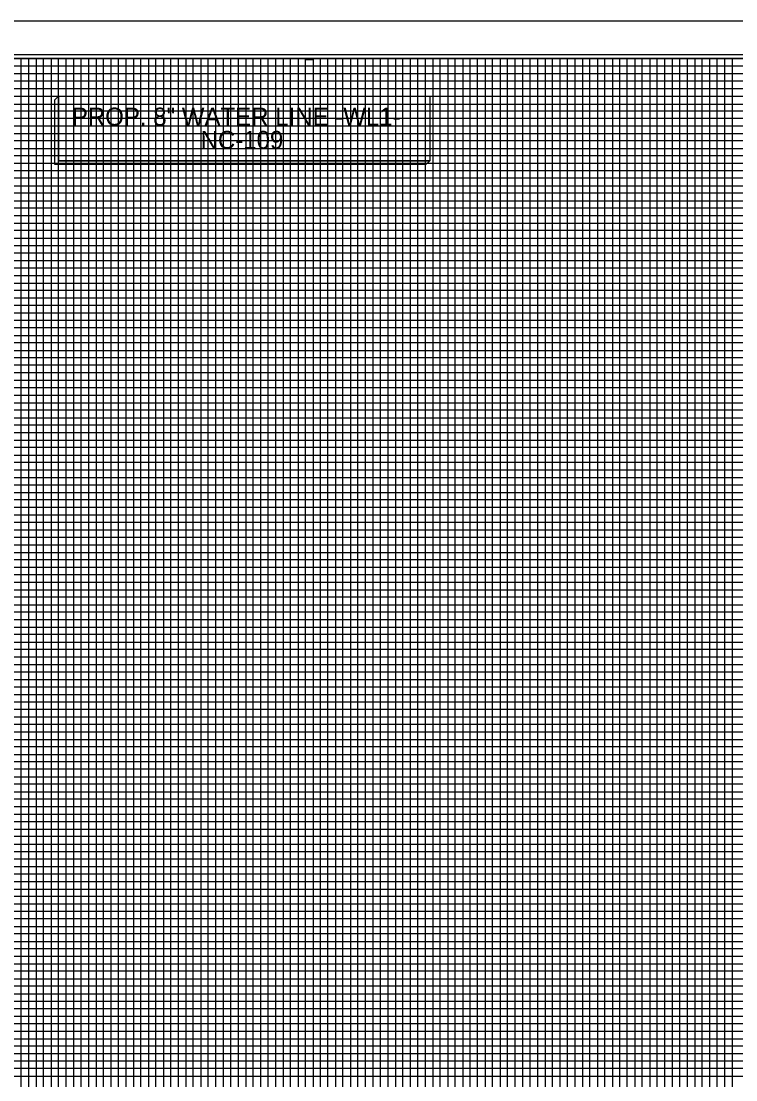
# Model space of a CAD drawing. Extents: x 3814791 to 3815465, y 1224203 to 1224643.
# Drawn here: x 3815088.1 to 3815279.1, y 1224360.2 to 1224643.2 of the extents above; entities that cross this region are included whole.
import ezdxf

# ---------------------------------------------------------------- set-up
doc = ezdxf.new("R2010")
doc.units = 0
for name, color, linetype in [('COGO Default Chain', 7, 'Continuous'), ('Exist Roads EOP', 7, 'Continuous'), ('Pattern 49', 7, 'Continuous'), ('Scratch_Level_1', 7, 'Continuous')]:
    doc.layers.add(name, color=color, linetype=linetype)

msp = doc.modelspace()

# ---------------------------------------------------------------- linework, layer by layer
at = {"layer": 'COGO Default Chain'}
for p, q in [((3815097.11, 1224622.19), (3815098.11, 1224623.19)), ((3815197.29, 1224605.91), (3815196.29, 1224604.91)), ((3815197.29, 1224605.91), (3815196.29, 1224604.91))]:
    msp.add_line(p, q, dxfattribs=at)
msp.add_lwpolyline([(3815098.11, 1224623.19), (3815197.29, 1224623.19), (3815197.29, 1224605.91), (3815098.11, 1224605.91)], close=True, dxfattribs=at)
for points in [[(3815098.11, 1224623.19), (3815098.11, 1224605.91), (3815197.29, 1224605.91)], [(3815196.29, 1224604.91), (3815097.11, 1224604.91), (3815097.11, 1224622.19)]]:
    msp.add_lwpolyline(points, dxfattribs=at)
at = {"layer": 'Exist Roads EOP'}
for p, q in [((3814878.11, 1224633.21), (3815378.11, 1224633.21)), ((3815438.11, 1224561.21), (3814878.11, 1224561.21)), ((3814878.11, 1224559.21), (3815438.11, 1224559.21)), ((3815438.11, 1224551.21), (3814878.11, 1224551.21))]:
    msp.add_line(p, q, dxfattribs=at)
for points in [[(3815458.11, 1224633.21), (3814858.11, 1224633.21), (3814858.11, 1224213.21), (3815458.11, 1224213.21)], [(3814878.11, 1224633.21), (3814878.11, 1224223.21), (3815438.11, 1224223.21), (3815438.11, 1224578.19), (3815378.11, 1224578.19), (3815378.11, 1224633.21)]]:
    msp.add_lwpolyline(points, close=True, dxfattribs=at)
for points in [[(3815088.11, 1224223.21), (3815088.11, 1224633.21), (3815108.11, 1224633.21), (3815108.11, 1224223.21)], [(3815090.11, 1224223.21), (3815090.11, 1224633.21), (3815092.11, 1224633.21), (3815092.11, 1224223.21)], [(3815094.11, 1224223.21), (3815094.11, 1224633.21), (3815096.11, 1224633.21), (3815096.11, 1224223.21)], [(3815098.11, 1224223.21), (3815098.11, 1224633.21), (3815118.11, 1224633.21), (3815118.11, 1224223.21)], [(3815100.11, 1224223.21), (3815100.11, 1224633.21), (3815102.11, 1224633.21), (3815102.11, 1224223.21)], [(3815104.11, 1224223.21), (3815104.11, 1224633.21), (3815106.11, 1224633.21), (3815106.11, 1224223.21)], [(3815110.11, 1224223.21), (3815110.11, 1224633.21), (3815112.11, 1224633.21), (3815112.11, 1224223.21)], [(3815114.11, 1224223.21), (3815114.11, 1224633.21), (3815116.11, 1224633.21), (3815116.11, 1224223.21)], [(3815120.11, 1224223.21), (3815120.11, 1224633.21), (3815122.11, 1224633.21), (3815122.11, 1224223.21)], [(3815124.11, 1224223.21), (3815124.11, 1224633.21), (3815126.11, 1224633.21), (3815126.11, 1224223.21)], [(3815128.11, 1224223.21), (3815128.11, 1224633.21), (3815148.11, 1224633.21), (3815148.11, 1224223.21)], [(3815130.11, 1224223.21), (3815130.11, 1224633.21), (3815132.11, 1224633.21), (3815132.11, 1224223.21)], [(3815134.11, 1224223.21), (3815134.11, 1224633.21), (3815136.11, 1224633.21), (3815136.11, 1224223.21)], [(3815138.11, 1224223.21), (3815138.11, 1224633.21), (3815158.11, 1224633.21), (3815158.11, 1224223.21)], [(3815140.11, 1224223.21), (3815140.11, 1224633.21), (3815142.11, 1224633.21), (3815142.11, 1224223.21)], [(3815144.11, 1224223.21), (3815144.11, 1224633.21), (3815146.11, 1224633.21), (3815146.11, 1224223.21)], [(3815150.11, 1224223.21), (3815150.11, 1224633.21), (3815152.11, 1224633.21), (3815152.11, 1224223.21)], [(3815154.11, 1224223.21), (3815154.11, 1224633.21), (3815156.11, 1224633.21), (3815156.11, 1224223.21)], [(3815160.11, 1224223.21), (3815160.11, 1224633.21), (3815162.11, 1224633.21), (3815162.11, 1224223.21)], [(3815164.11, 1224223.21), (3815164.11, 1224632.97), (3815166.11, 1224632.97), (3815166.11, 1224223.21)], [(3815168.11, 1224223.21), (3815168.11, 1224633.21), (3815188.11, 1224633.21), (3815188.11, 1224223.21)], [(3815170.11, 1224223.21), (3815170.11, 1224633.21), (3815172.11, 1224633.21), (3815172.11, 1224223.21)], [(3815174.11, 1224223.21), (3815174.11, 1224633.21), (3815176.11, 1224633.21), (3815176.11, 1224223.21)], [(3815178.11, 1224223.21), (3815178.11, 1224633.21), (3815198.11, 1224633.21), (3815198.11, 1224223.21)], [(3815180.11, 1224223.21), (3815180.11, 1224633.21), (3815182.11, 1224633.21), (3815182.11, 1224223.21)], [(3815184.11, 1224223.21), (3815184.11, 1224633.21), (3815186.11, 1224633.21), (3815186.11, 1224223.21)], [(3815190.11, 1224223.21), (3815190.11, 1224633.21), (3815192.11, 1224633.21), (3815192.11, 1224223.21)], [(3815194.11, 1224223.21), (3815194.11, 1224633.21), (3815196.11, 1224633.21), (3815196.11, 1224223.21)], [(3815200.11, 1224223.21), (3815200.11, 1224633.21), (3815202.11, 1224633.21), (3815202.11, 1224223.21)], [(3815204.11, 1224223.21), (3815204.11, 1224633.21), (3815206.11, 1224633.21), (3815206.11, 1224223.21)], [(3815208.11, 1224223.21), (3815208.11, 1224633.21), (3815228.11, 1224633.21), (3815228.11, 1224223.21)], [(3815210.11, 1224223.21), (3815210.11, 1224633.21), (3815212.11, 1224633.21), (3815212.11, 1224223.21)], [(3815214.11, 1224223.21), (3815214.11, 1224633.21), (3815216.11, 1224633.21), (3815216.11, 1224223.21)], [(3815218.11, 1224223.21), (3815218.11, 1224633.21), (3815238.11, 1224633.21), (3815238.11, 1224223.21)], [(3815220.11, 1224223.21), (3815220.11, 1224633.21), (3815222.11, 1224633.21), (3815222.11, 1224223.21)], [(3815224.11, 1224223.21), (3815224.11, 1224633.21), (3815226.11, 1224633.21), (3815226.11, 1224223.21)], [(3815230.11, 1224223.21), (3815230.11, 1224633.21), (3815232.11, 1224633.21), (3815232.11, 1224223.21)], [(3815234.11, 1224223.21), (3815234.11, 1224633.21), (3815236.11, 1224633.21), (3815236.11, 1224223.21)], [(3815240.11, 1224223.21), (3815240.11, 1224633.21), (3815242.11, 1224633.21), (3815242.11, 1224223.21)], [(3815244.11, 1224223.21), (3815244.11, 1224633.21), (3815246.11, 1224633.21), (3815246.11, 1224223.21)], [(3815248.11, 1224223.21), (3815248.11, 1224633.21), (3815268.11, 1224633.21), (3815268.11, 1224223.21)], [(3815250.11, 1224223.21), (3815250.11, 1224633.21), (3815252.11, 1224633.21), (3815252.11, 1224223.21)], [(3815254.11, 1224223.21), (3815254.11, 1224633.21), (3815256.11, 1224633.21), (3815256.11, 1224223.21)], [(3815258.11, 1224223.21), (3815258.11, 1224633.21), (3815278.11, 1224633.21), (3815278.11, 1224223.21)], [(3815260.11, 1224223.21), (3815260.11, 1224633.21), (3815262.11, 1224633.21), (3815262.11, 1224223.21)], [(3815264.11, 1224223.21), (3815264.11, 1224633.21), (3815266.11, 1224633.21), (3815266.11, 1224223.21)], [(3815270.11, 1224223.21), (3815270.11, 1224633.21), (3815272.11, 1224633.21), (3815272.11, 1224223.21)], [(3815274.11, 1224223.21), (3815274.11, 1224633.21), (3815276.11, 1224633.21), (3815276.11, 1224223.21)], [(3815378.09, 1224631.21), (3814878.11, 1224631.21), (3814878.11, 1224629.21), (3815378.09, 1224629.21)], [(3815378.09, 1224627.21), (3814878.11, 1224627.21), (3814878.11, 1224625.21), (3815378.09, 1224625.21)], [(3815378.09, 1224603.21), (3814858.15, 1224603.21), (3814858.15, 1224623.19), (3815378.09, 1224623.19)], [(3815378.09, 1224620.91), (3814878.11, 1224620.91), (3814878.11, 1224619.21), (3815378.09, 1224619.21)], [(3815378.09, 1224617.21), (3814878.11, 1224617.21), (3814878.11, 1224615.21), (3815378.09, 1224615.21)], [(3814858.11, 1224613.21), (3815378.09, 1224613.21)], [(3815378.09, 1224611.21), (3814878.11, 1224611.21), (3814878.11, 1224609.21), (3815378.09, 1224609.21)], [(3815378.11, 1224607.21), (3814878.11, 1224607.21), (3814878.11, 1224605.21), (3815378.09, 1224605.21)], [(3815378.09, 1224601.21), (3814878.11, 1224601.21), (3814878.11, 1224599.21), (3815378.09, 1224599.21)], [(3815378.09, 1224597.21), (3814878.11, 1224597.21), (3814878.11, 1224595.21), (3815378.09, 1224595.21)], [(3815378.09, 1224593.21), (3814858.11, 1224593.21), (3814858.11, 1224573.19), (3815458.11, 1224573.19)], [(3815378.09, 1224591.21), (3814878.11, 1224591.21), (3814878.11, 1224589.21), (3815378.09, 1224589.21)], [(3815378.09, 1224587.21), (3814878.11, 1224587.21), (3814878.11, 1224585.21), (3815378.09, 1224585.21)], [(3815458.11, 1224563.21), (3814858.11, 1224563.21), (3814858.11, 1224583.21), (3815378.09, 1224583.21)], [(3815378.09, 1224581.21), (3814878.11, 1224581.21), (3814878.11, 1224579.21), (3815378.09, 1224579.21)], [(3815438.11, 1224577.21), (3814878.11, 1224577.21), (3814878.11, 1224577.21), (3814878.11, 1224569.21), (3815438.11, 1224569.21)], [(3815438.11, 1224577.21), (3814878.11, 1224577.21), (3814878.11, 1224577.21), (3814878.11, 1224569.21), (3815458.11, 1224569.21)], [(3814878.11, 1224575.21), (3815438.11, 1224575.21)], [(3815438.11, 1224571.21), (3814878.11, 1224571.21)], [(3815438.11, 1224567.21), (3814878.11, 1224567.21), (3814878.11, 1224565.21), (3815438.11, 1224565.21)], [(3815438.11, 1224557.21), (3814878.11, 1224557.21), (3814878.11, 1224555.21), (3815438.11, 1224555.21)], [(3815458.11, 1224553.21), (3814858.11, 1224553.21), (3814858.11, 1224533.21), (3815458.11, 1224533.21)], [(3815438.11, 1224549.21), (3814878.11, 1224549.21), (3814878.11, 1224547.21), (3815438.11, 1224547.21)], [(3815438.11, 1224545.21), (3814878.11, 1224545.21)], [(3815458.11, 1224523.21), (3814858.11, 1224523.21), (3814858.11, 1224543.21), (3815458.11, 1224543.21)], [(3814878.11, 1224541.21), (3815438.11, 1224541.21)], [(3815438.11, 1224539.21), (3814878.11, 1224539.21), (3814878.11, 1224537.21), (3815438.11, 1224537.21)], [(3815438.11, 1224535.21), (3814878.11, 1224535.21), (3814878.11, 1224531.21), (3815438.11, 1224531.21)], [(3815438.11, 1224529.21), (3814878.11, 1224529.21), (3814878.11, 1224527.21), (3815438.11, 1224527.21)], [(3815438.11, 1224525.21), (3814878.11, 1224525.21), (3814878.11, 1224521.21), (3815438.11, 1224521.21)], [(3815438.11, 1224519.21), (3814878.11, 1224519.21), (3814878.11, 1224517.21), (3815438.11, 1224517.21)], [(3815458.11, 1224513.21), (3814858.11, 1224513.21), (3814858.11, 1224493.21), (3815458.11, 1224493.21)], [(3815438.11, 1224515.21), (3814878.11, 1224515.21), (3814878.11, 1224511.21), (3815438.11, 1224511.21)], [(3815438.11, 1224509.21), (3814878.11, 1224509.21), (3814878.11, 1224507.21), (3815438.11, 1224507.21)], [(3815438.11, 1224505.21), (3814878.11, 1224505.21), (3814878.11, 1224501.21), (3815438.11, 1224501.21)], [(3815458.11, 1224483.21), (3814858.11, 1224483.21), (3814858.11, 1224503.21), (3815458.11, 1224503.21)], [(3815438.11, 1224499.21), (3814878.11, 1224499.21), (3814878.11, 1224497.21), (3815438.11, 1224497.21)], [(3815438.11, 1224495.21), (3814878.11, 1224495.21), (3814878.11, 1224491.21), (3815438.11, 1224491.21)], [(3815438.11, 1224489.21), (3814878.11, 1224489.21), (3814878.11, 1224487.21), (3815438.11, 1224487.21)], [(3815438.11, 1224485.21), (3814878.11, 1224485.21), (3814878.11, 1224481.21), (3815438.11, 1224481.21)], [(3815438.11, 1224479.21), (3814878.11, 1224479.21), (3814878.11, 1224477.21), (3815438.11, 1224477.21)], [(3815458.11, 1224473.21), (3814858.11, 1224473.21), (3814858.11, 1224453.21), (3815458.11, 1224453.21)], [(3815438.11, 1224475.21), (3814878.11, 1224475.21), (3814878.11, 1224471.21), (3815438.11, 1224471.21)], [(3815438.11, 1224469.21), (3814878.11, 1224469.21), (3814878.11, 1224467.21), (3815438.11, 1224467.21)], [(3815438.11, 1224465.21), (3814878.11, 1224465.21), (3814878.11, 1224461.21), (3815438.11, 1224461.21)], [(3815458.11, 1224443.21), (3814858.11, 1224443.21), (3814858.11, 1224463.21), (3815458.11, 1224463.21)], [(3815438.11, 1224459.21), (3814878.11, 1224459.21), (3814878.11, 1224457.21), (3815438.11, 1224457.21)], [(3815438.11, 1224455.21), (3814878.11, 1224455.21), (3814878.11, 1224451.21), (3815438.11, 1224451.21)], [(3815438.11, 1224449.21), (3814878.11, 1224449.21), (3814878.11, 1224447.21), (3815438.11, 1224447.21)], [(3815438.11, 1224445.21), (3814878.11, 1224445.21), (3814878.11, 1224441.21), (3815438.11, 1224441.21)], [(3815438.11, 1224439.21), (3814878.11, 1224439.21), (3814878.11, 1224437.21), (3815438.11, 1224437.21)], [(3815438.11, 1224435.21), (3814878.11, 1224435.21), (3814878.11, 1224431.21), (3815438.11, 1224431.21)], [(3815458.11, 1224433.21), (3814858.11, 1224433.21), (3814858.11, 1224413.21), (3815458.11, 1224413.21)], [(3815438.11, 1224429.21), (3814878.11, 1224429.21), (3814878.11, 1224427.21), (3815438.11, 1224427.21)], [(3815438.11, 1224425.21), (3814878.11, 1224425.21)], [(3815458.11, 1224403.21), (3814858.11, 1224403.21), (3814858.11, 1224423.21), (3815458.11, 1224423.21)], [(3814878.11, 1224421.21), (3815438.11, 1224421.21)], [(3815438.11, 1224419.21), (3814878.11, 1224419.21), (3814878.11, 1224417.21), (3815438.11, 1224417.21)], [(3815438.11, 1224415.21), (3814878.11, 1224415.21), (3814878.11, 1224411.21), (3815438.11, 1224411.21)], [(3815438.11, 1224409.21), (3814878.11, 1224409.21), (3814878.11, 1224407.21), (3815438.11, 1224407.21)], [(3815438.11, 1224405.21), (3814878.11, 1224405.21), (3814878.11, 1224401.21), (3815438.11, 1224401.21)], [(3815438.11, 1224399.21), (3814878.11, 1224399.21), (3814878.11, 1224397.21), (3815438.11, 1224397.21)], [(3815438.11, 1224395.21), (3814878.11, 1224395.21), (3814878.11, 1224391.21), (3815438.11, 1224391.21)], [(3815458.11, 1224393.21), (3814858.11, 1224393.21), (3814858.11, 1224373.21), (3815458.11, 1224373.21)], [(3815438.11, 1224389.21), (3814878.11, 1224389.21), (3814878.11, 1224387.21), (3815438.11, 1224387.21)], [(3815458.11, 1224363.21), (3814858.11, 1224363.21), (3814858.11, 1224383.21), (3815458.11, 1224383.21)], [(3815438.11, 1224385.21), (3814878.11, 1224385.21), (3814878.11, 1224381.21), (3815438.11, 1224381.21)], [(3815438.11, 1224379.21), (3814878.11, 1224379.21), (3814878.11, 1224377.21), (3815438.11, 1224377.21)], [(3815438.11, 1224375.21), (3814878.11, 1224375.21), (3814878.11, 1224371.21), (3815438.11, 1224371.21)], [(3815438.11, 1224369.21), (3814878.11, 1224369.21), (3814878.11, 1224367.21), (3815438.11, 1224367.21)], [(3815438.11, 1224365.21), (3814878.11, 1224365.21), (3814878.11, 1224361.21), (3815438.11, 1224361.21)]]:
    msp.add_lwpolyline(points, dxfattribs=at)
at = {"layer": 'Pattern 49'}
msp.add_lwpolyline([(3815463.11, 1224634.23), (3814796.51, 1224634.23), (3814796.51, 1224212.19), (3815463.11, 1224212.19)], close=True, dxfattribs=at)
at = {"layer": 'Scratch_Level_1'}
msp.add_lwpolyline([(3815464.91, 1224643.21), (3814791.31, 1224643.21), (3814791.31, 1224203.21), (3815464.91, 1224203.21)], close=True, dxfattribs=at)

# ---------------------------------------------------------------- texts
at = {"layer": 'COGO Default Chain'}
for s, p in [('PROP. 8" WATER LINE -WL1-', (3815101.65, 1224615.29)), ('NC-109', (3815136.05, 1224609.07))]:
    msp.add_text(s, height=4.8, rotation=360, dxfattribs=at).set_placement(p)

doc.saveas('drawing.dxf')
